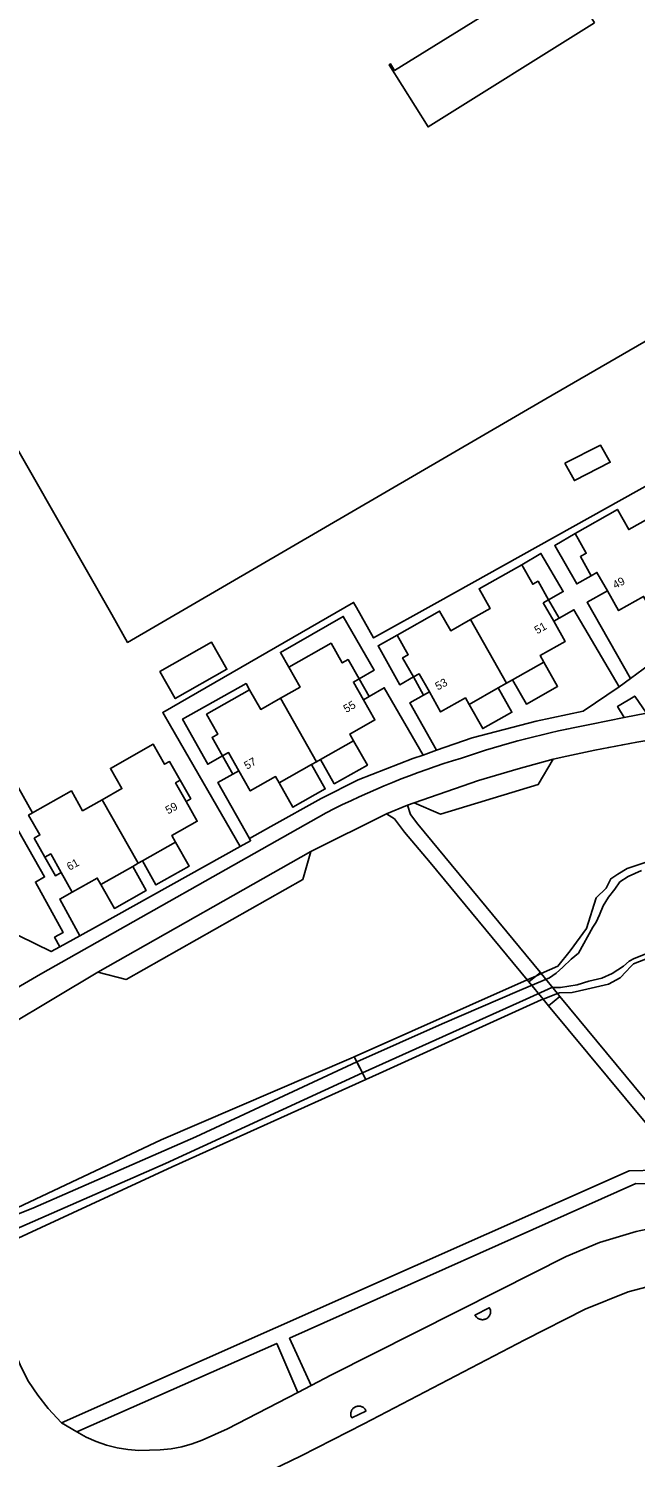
# Model space of a CAD drawing. Extents: x 158132 to 159664, y 385256 to 387218.
# Drawn here: x 158829.4 to 158905.2, y 386531.1 to 386709.7 of the extents above; entities that cross this region are included whole.
import ezdxf

# ---------------------------------------------------------------- set-up
doc = ezdxf.new("R2010")
doc.units = 0
for name, color, linetype in [('IMGEO_Berm_groen', 7, 'Continuous'), ('IMGEO_Dek', 7, 'Continuous'), ('IMGEO_Erf', 7, 'Continuous'), ('IMGEO_Gemengd_bos', 7, 'Continuous'), ('IMGEO_Groenvoorziening', 7, 'Continuous'), ('IMGEO_Oever', 7, 'Continuous'), ('IMGEO_Open_loods', 7, 'Continuous'), ('IMGEO_Pand', 7, 'Continuous'), ('IMGEO_Pand_nummerreeks', 7, 'Continuous'), ('IMGEO_Parkeervlak_open', 7, 'Continuous'), ('IMGEO_Rijbaan_lokaal_gesloten', 7, 'Continuous'), ('IMGEO_Stuw', 7, 'Continuous'), ('IMGEO_Verkeerseiland_gesloten', 7, 'Continuous'), ('IMGEO_Voetpad_open', 7, 'Continuous'), ('IMGEO_Waterloop', 7, 'Continuous')]:
    doc.layers.add(name, color=color, linetype=linetype)

msp = doc.modelspace()

# ---------------------------------------------------------------- linework, layer by layer
at = {"layer": 'IMGEO_Berm_groen'}
for points in [[(158888.13, 386552.01), (158896.53, 386556.23), (158900.72, 386557.98), (158905.3, 386559.36), (158909.03, 386560.17), (158911.81, 386560.55), (158915.94, 386560.75), (158916.6, 386560.75), (158912.81, 386565.3), (158905.26, 386565.37), (158862.01, 386546.04), (158864.7, 386540.13), (158867.23, 386541.45)], [(158863.03, 386539.27), (158860.41, 386545.38), (158835.44, 386534.34), (158836.63, 386533.68), (158837.87, 386533.13), (158839.16, 386532.69), (158840.47, 386532.35), (158841.81, 386532.13), (158843.17, 386532.02), (158844.52, 386532.03), (158845.87, 386532.07), (158847.21, 386532.22), (158848.54, 386532.48), (158849.84, 386532.84), (158851.11, 386533.3), (158854.27, 386534.72)]]:
    msp.add_lwpolyline(points, close=True, dxfattribs=at)
at = {"layer": 'IMGEO_Dek'}
msp.add_lwpolyline([(158893.42, 386591.59), (158893.28, 386591.76), (158892.74, 386591.28), (158891.9, 386590.55), (158893.66, 386588.4), (158894.35, 386587.56), (158895.75, 386588.72), (158895.45, 386589.1)], close=True, dxfattribs=at)
at = {"layer": 'IMGEO_Erf'}
for points in [[(158934.18, 386686.67), (158894, 386663.42), (158841.79, 386632.99), (158839.81, 386636.46), (158826.35, 386660.11)], [(158824.99, 386620.4), (158829.92, 386611.68), (158834.77, 386614.42), (158836.17, 386611.95), (158838.62, 386613.33), (158841.07, 386614.72), (158839.65, 386617.23), (158844.99, 386620.25), (158846.41, 386617.75), (158847.03, 386618.1), (158848.36, 386615.75), (158849.67, 386613.44), (158849.08, 386613.11), (158850.48, 386610.64), (158847.3, 386608.84), (158847.77, 386608.01), (158849.46, 386605.02), (158845.33, 386602.68), (158843.64, 386605.67), (158843.12, 386605.38), (158842.42, 386604.98), (158844.11, 386601.99), (158840.13, 386599.74), (158838.44, 386602.73), (158837.99, 386603.53), (158834.88, 386601.77), (158833.32, 386600.9), (158835.84, 386596.33), (158838.15, 386597.61), (158855.83, 386607.47), (158847.13, 386622.56), (158846.17, 386624.23), (158870.01, 386637.98), (158870.37, 386637.36), (158872.5, 386633.54), (158880.44, 386637.97), (158907.83, 386653.27)], [(158808.08, 386606.17), (158832.23, 386594.34), (158833.32, 386594.94), (158832.66, 386596.14), (158833.74, 386596.73), (158830.27, 386603.03), (158831.43, 386603.67), (158822.65, 386619.06)]]:
    msp.add_lwpolyline(points, dxfattribs=at)
for points in [[(158896.37, 386655.36), (158900.83, 386657.64), (158902.04, 386655.49), (158897.58, 386653.21)], [(158923.8, 386642.26), (158919.5, 386649.38), (158917.3, 386648.14), (158918.62, 386645.8), (158915.52, 386644.04), (158915.99, 386643.21), (158917.67, 386640.24), (158913.41, 386637.83), (158911.73, 386640.8), (158911.3, 386640.55), (158910.53, 386640.12), (158912.21, 386637.15), (158908.33, 386634.96), (158906.66, 386637.93), (158906.2, 386638.73), (158903.08, 386636.96), (158901.69, 386639.42), (158899.16, 386637.99), (158904.56, 386628.48), (158911.71, 386633.74), (158918.74, 386639), (158921.04, 386640.5)], [(158897.65, 386646.61), (158895.11, 386645.11), (158897.86, 386640.29), (158899.68, 386641.32), (158898.32, 386643.71), (158899.06, 386644.12)], [(158893.39, 386644.1), (158890.99, 386642.69), (158892.37, 386640.25), (158893.04, 386640.63), (158894.35, 386638.3), (158896.18, 386639.34)], [(158897.52, 386637.06), (158895.65, 386636), (158894.99, 386635.63), (158896.42, 386633.11), (158893.3, 386631.35), (158893.76, 386630.52), (158895.48, 386627.49), (158891.58, 386625.28), (158889.86, 386628.32), (158889.1, 386627.88), (158888.06, 386627.29), (158889.77, 386624.26), (158889.46, 386624.09), (158886.13, 386622.21), (158884.42, 386625.24), (158883.96, 386626.04), (158880.87, 386624.29), (158879.46, 386626.8), (158878.75, 386626.4), (158877.03, 386625.44), (158880.35, 386619.5), (158884.79, 386621.05), (158892.81, 386623.14), (158898.68, 386624.38), (158903.15, 386627.44)], [(158868.71, 386636.24), (158860.87, 386631.73), (158861.9, 386629.89), (158867.19, 386632.88), (158868.58, 386630.42), (158869.31, 386630.84), (158870.68, 386628.42), (158872.57, 386629.51)], [(158875.43, 386633.9), (158873.05, 386632.56), (158875.76, 386627.7), (158877.48, 386628.66), (158876.12, 386631.05), (158876.82, 386631.45)], [(158845.82, 386629.34), (158852.28, 386633), (158854.19, 386629.63), (158847.73, 386625.97)], [(158851.65, 386624.01), (158857.02, 386627.05), (158856.58, 386627.83), (158848.65, 386623.41), (158851.8, 386617.76), (158853.65, 386618.79), (158852.34, 386621.11), (158853.06, 386621.52)], [(158860.7, 386615.44), (158860.27, 386616.21), (158857.1, 386614.42), (158855.67, 386616.94), (158854.94, 386616.53), (158853.07, 386615.48), (158856.99, 386608.46), (158859.68, 386609.98), (158865.97, 386613.47), (158870.56, 386615.79), (158877.39, 386618.47), (158878.67, 386618.91), (158873.84, 386627.31), (158871.93, 386626.21), (158871.23, 386625.82), (158872.66, 386623.29), (158869.53, 386621.52), (158869.99, 386620.7), (158871.72, 386617.65), (158867.58, 386615.31), (158865.86, 386618.36), (158865.35, 386618.07), (158864.73, 386617.72), (158866.46, 386614.67), (158862.43, 386612.39)]]:
    msp.add_lwpolyline(points, close=True, dxfattribs=at)
at = {"layer": 'IMGEO_Gemengd_bos'}
msp.add_lwpolyline([(158826.35, 386660.11), (158839.81, 386636.46), (158841.79, 386632.99), (158894, 386663.42), (158934.18, 386686.67), (158952.31, 386658.15), (159000, 386688.47), (159011.16, 386695.57), (159011.4, 386697), (159012.14, 386697.47), (159010.3, 386700.29), (159011.17, 386700.87), (158997.52, 386722.16)], dxfattribs=at)
msp.add_lwpolyline([(158900.1, 386710.42), (158879.3, 386697.4), (158874.46, 386705.16), (158874.63, 386705.26), (158875.13, 386704.45), (158895.64, 386717.2), (158895.09, 386718.08), (158895.26, 386718.18)], close=True, dxfattribs=at)
at = {"layer": 'IMGEO_Groenvoorziening'}
for points in [[(158902.97, 386624.98), (158903.79, 386623.6), (158906.57, 386624.16), (158905.11, 386626.27)], [(158894.35, 386587.56), (158895.75, 386588.72), (158895.45, 386589.1), (158893.66, 386588.4)]]:
    msp.add_lwpolyline(points, close=True, dxfattribs=at)
for points in [[(158894.9, 386618.38), (158893.06, 386615.24), (158880.85, 386611.52), (158877.57, 386612.95), (158876.73, 386612.63), (158877.11, 386611.46), (158878.02, 386610.26), (158893.28, 386591.76), (158893.42, 386591.59), (158895.52, 386592.52), (158897.04, 386594.45), (158899.07, 386597.22), (158900.3, 386601.08), (158901.55, 386602.26), (158901.83, 386602.85), (158902.12, 386603.45), (158903, 386604.04), (158904.16, 386604.73), (158907.15, 386605.72)], [(158869.71, 386581.02), (158870.09, 386581.19), (158891.69, 386590.81), (158879.56, 386605.47), (158876.37, 386609.29), (158875.1, 386610.95), (158874.11, 386611.57), (158864.67, 386606.85), (158863.68, 386603.37), (158841.59, 386590.87), (158838.06, 386591.79), (158821.34, 386581.8)], [(158910.42, 386594.96), (158904.95, 386592.82), (158904.56, 386592.44), (158904.05, 386591.87), (158903.27, 386591.08), (158901.81, 386590.29), (158899.14, 386589.66), (158897.31, 386589.25), (158895.7, 386589.2), (158895.45, 386589.1), (158895.75, 386588.72), (158913.24, 386567.6)], [(158818.27, 386573.98), (158823.22, 386558.59), (158827.67, 386544.4), (158828.46, 386542.48), (158829.43, 386540.64), (158830.56, 386538.9), (158831.85, 386537.27), (158833.53, 386535.48), (158904.42, 386566.95), (158911.33, 386567.1), (158894.35, 386587.56), (158893.66, 386588.4), (158893.44, 386588.31), (158873.2, 386579.11), (158871.54, 386578.36), (158847.34, 386567.44), (158827.03, 386558.04), (158825.5, 386558.41), (158824.82, 386559.92), (158825.76, 386561.3), (158845.97, 386570.81), (158869.71, 386581.02)], [(158936.96, 386525.53), (158923.1, 386553.6), (158923.02, 386553.59), (158913.93, 386553.63), (158910.67, 386553.29), (158907.44, 386552.68), (158904.28, 386551.82), (158898.92, 386549.67), (158891.4, 386545.83), (158871.3, 386535.33), (158863.44, 386531.35), (158857.17, 386528.29)]]:
    msp.add_lwpolyline(points, dxfattribs=at)
msp.add_arc((158937.68, 386434.2), 189.08, 85.8307, 103.0757, dxfattribs=at)
at = {"layer": 'IMGEO_Oever'}
for points in [[(158907.15, 386605.72), (158904.16, 386604.73), (158903, 386604.04), (158902.12, 386603.45), (158901.83, 386602.85), (158901.55, 386602.26), (158900.3, 386601.08), (158899.07, 386597.22), (158897.04, 386594.45), (158895.52, 386592.52), (158893.42, 386591.59), (158892.74, 386591.28), (158891.69, 386590.81), (158870.09, 386581.19), (158870.4, 386580.59), (158881.06, 386585.32), (158890.71, 386589.5), (158894.45, 386591.05), (158895.3, 386591.67), (158896.12, 386592.39), (158897.16, 386593.38), (158898.09, 386594.17), (158899.89, 386597.41), (158900.27, 386598.01), (158900.7, 386598.93), (158901.16, 386600.05), (158901.83, 386601.16), (158902.61, 386602.16), (158903.25, 386603.07), (158904.27, 386603.75), (158905.97, 386604.5)], [(158906.39, 386594.02), (158905.05, 386593.49), (158904.42, 386593.17), (158903.71, 386592.54), (158902.3, 386591.62), (158900.98, 386591.04), (158899.37, 386590.65), (158897.93, 386590.21), (158895.82, 386589.86), (158894.76, 386589.84), (158891.54, 386588.41), (158871.12, 386579.19), (158871.54, 386578.36), (158873.2, 386579.11), (158893.44, 386588.31), (158893.66, 386588.4), (158895.45, 386589.1), (158895.7, 386589.2), (158897.31, 386589.25), (158899.14, 386589.66), (158901.81, 386590.29), (158903.27, 386591.08), (158904.05, 386591.87), (158904.56, 386592.44), (158904.95, 386592.82), (158910.42, 386594.96)]]:
    msp.add_lwpolyline(points, dxfattribs=at)
msp.add_lwpolyline([(158871.54, 386578.36), (158871.12, 386579.19), (158846.53, 386567.85), (158826.88, 386559.26), (158826.46, 386559.47), (158826.22, 386560.01), (158826.18, 386560.43), (158826.51, 386560.91), (158829.95, 386562.3), (158850.3, 386571.19), (158870.4, 386580.59), (158870.09, 386581.19), (158869.71, 386581.02), (158845.97, 386570.81), (158825.76, 386561.3), (158824.82, 386559.92), (158825.5, 386558.41), (158827.03, 386558.04), (158847.34, 386567.44)], close=True, dxfattribs=at)
at = {"layer": 'IMGEO_Open_loods'}
msp.add_lwpolyline([(158900.1, 386710.42), (158895.26, 386718.18), (158895.09, 386718.08), (158895.64, 386717.2), (158875.13, 386704.45), (158874.63, 386705.26), (158874.46, 386705.16), (158879.3, 386697.4)], close=True, dxfattribs=at)
at = {"layer": 'IMGEO_Pand'}
for points in [[(158896.37, 386655.36), (158897.58, 386653.21), (158902.04, 386655.49), (158900.83, 386657.64)], [(158906.82, 386648.48), (158904.36, 386647.09), (158902.94, 386649.6), (158897.65, 386646.61), (158899.06, 386644.12), (158898.32, 386643.71), (158899.68, 386641.32), (158900.39, 386641.72), (158901.69, 386639.42), (158903.08, 386636.96), (158906.2, 386638.73), (158906.66, 386637.93), (158910.53, 386640.12), (158911.3, 386640.55)], [(158893.69, 386637.93), (158894.35, 386638.3), (158893.04, 386640.63), (158892.37, 386640.25), (158890.99, 386642.69), (158885.68, 386639.69), (158887.07, 386637.23), (158884.6, 386635.83), (158889.1, 386627.88), (158889.86, 386628.32), (158893.76, 386630.52), (158893.3, 386631.35), (158896.42, 386633.11), (158894.99, 386635.63)], [(158884.6, 386635.83), (158882.13, 386634.44), (158880.74, 386636.9), (158875.43, 386633.9), (158876.82, 386631.45), (158876.12, 386631.05), (158877.48, 386628.66), (158878.18, 386629.06), (158879.46, 386626.8), (158880.87, 386624.29), (158883.96, 386626.04), (158884.42, 386625.24), (158888.06, 386627.29), (158889.1, 386627.88)], [(158847.73, 386625.97), (158854.19, 386629.63), (158852.28, 386633), (158845.82, 386629.34)], [(158871.23, 386625.82), (158869.98, 386628.03), (158870.68, 386628.42), (158869.31, 386630.84), (158868.58, 386630.42), (158867.19, 386632.88), (158861.9, 386629.89), (158863.32, 386627.39), (158860.86, 386626), (158865.35, 386618.07), (158865.86, 386618.36), (158869.99, 386620.7), (158869.53, 386621.52), (158872.66, 386623.29)], [(158860.86, 386626), (158858.4, 386624.61), (158857.02, 386627.05), (158851.65, 386624.01), (158853.06, 386621.52), (158852.34, 386621.11), (158853.65, 386618.79), (158854.39, 386619.21), (158855.67, 386616.94), (158857.1, 386614.42), (158860.27, 386616.21), (158860.7, 386615.44), (158864.73, 386617.72), (158865.35, 386618.07)], [(158847.77, 386615.42), (158848.36, 386615.75), (158847.03, 386618.1), (158846.41, 386617.75), (158844.99, 386620.25), (158839.65, 386617.23), (158841.07, 386614.72), (158838.62, 386613.33), (158843.12, 386605.38), (158843.64, 386605.67), (158847.77, 386608.01), (158847.3, 386608.84), (158850.48, 386610.64), (158849.08, 386613.11)], [(158838.62, 386613.33), (158836.17, 386611.95), (158834.77, 386614.42), (158829.92, 386611.68), (158829.43, 386611.4), (158830.84, 386608.92), (158830.13, 386608.52), (158831.47, 386606.15), (158832.18, 386606.55), (158833.49, 386604.23), (158834.88, 386601.77), (158837.99, 386603.53), (158838.44, 386602.73), (158842.42, 386604.98), (158843.12, 386605.38)]]:
    msp.add_lwpolyline(points, close=True, dxfattribs=at)
at = {"layer": 'IMGEO_Parkeervlak_open'}
for points in [[(158894.9, 386618.38), (158890.53, 386617.17), (158885.6, 386615.73), (158877.57, 386612.95), (158880.85, 386611.52), (158893.06, 386615.24)], [(158864.67, 386606.85), (158838.06, 386591.79), (158841.59, 386590.87), (158863.68, 386603.37)]]:
    msp.add_lwpolyline(points, close=True, dxfattribs=at)
at = {"layer": 'IMGEO_Rijbaan_lokaal_gesloten'}
for points in [[(158953.96, 386625.78), (158944.85, 386626.47), (158936.8, 386626.71), (158925.72, 386626.16), (158917.97, 386625.61), (158906.57, 386624.16), (158903.79, 386623.6), (158899.7, 386622.78)], [(158821.34, 386581.8), (158838.06, 386591.79), (158864.67, 386606.85), (158874.11, 386611.57), (158876.73, 386612.63), (158877.57, 386612.95), (158885.6, 386615.73), (158890.53, 386617.17), (158894.9, 386618.38)], [(158866.59, 386611.69), (158830.89, 386591.54), (158824.65, 386587.92), (158820.79, 386585.6), (158819.2, 386584.7), (158818.52, 386584.29)], [(158857.17, 386528.29), (158863.44, 386531.35), (158871.3, 386535.33), (158891.4, 386545.83), (158898.92, 386549.67), (158904.28, 386551.82), (158907.44, 386552.68), (158910.67, 386553.29), (158913.93, 386553.63), (158923.02, 386553.59), (158923.1, 386553.6), (158925.12, 386553.7), (158925.18, 386553.7), (158927.78, 386553.93), (158944.36, 386560.03)], [(158905.3, 386559.36), (158900.72, 386557.98), (158896.53, 386556.23), (158888.13, 386552.01), (158867.23, 386541.45), (158864.7, 386540.13), (158863.03, 386539.27), (158854.27, 386534.72), (158851.11, 386533.3), (158849.84, 386532.84), (158848.54, 386532.48), (158847.21, 386532.22), (158845.87, 386532.07), (158844.52, 386532.03), (158843.17, 386532.02), (158841.81, 386532.13), (158840.47, 386532.35), (158839.16, 386532.69), (158837.87, 386533.13), (158836.63, 386533.68), (158835.44, 386534.34), (158833.53, 386535.48), (158831.85, 386537.27), (158830.56, 386538.9), (158829.43, 386540.64), (158828.46, 386542.48)]]:
    msp.add_lwpolyline(points, dxfattribs=at)
for points in [[(158887.03, 386548.97), (158887, 386548.89), (158886.95, 386548.82), (158886.9, 386548.75), (158886.84, 386548.68), (158886.78, 386548.62), (158886.71, 386548.56), (158886.64, 386548.51), (158886.56, 386548.47), (158886.48, 386548.43), (158886.4, 386548.4), (158886.31, 386548.38), (158886.23, 386548.36), (158886.14, 386548.35), (158886.05, 386548.35), (158885.96, 386548.36), (158885.88, 386548.38), (158885.79, 386548.4), (158885.71, 386548.43), (158885.63, 386548.47), (158885.55, 386548.51), (158885.48, 386548.56), (158885.41, 386548.62), (158885.35, 386548.68), (158885.16, 386548.9), (158886.94, 386549.84), (158887.09, 386549.58), (158887.11, 386549.49), (158887.11, 386549.41), (158887.11, 386549.32), (158887.1, 386549.23), (158887.09, 386549.14), (158887.06, 386549.06)], [(158871.43, 386537.18), (158871.54, 386536.9), (158869.8, 386536.09), (158869.66, 386536.33), (158869.65, 386536.42), (158869.64, 386536.5), (158869.64, 386536.59), (158869.65, 386536.68), (158869.67, 386536.76), (158869.69, 386536.85), (158869.72, 386536.93), (158869.75, 386537.01), (158869.8, 386537.08), (158869.85, 386537.15), (158869.9, 386537.22), (158869.96, 386537.28), (158870.03, 386537.34), (158870.1, 386537.39), (158870.17, 386537.43), (158870.25, 386537.47), (158870.33, 386537.5), (158870.42, 386537.52), (158870.5, 386537.54), (158870.59, 386537.55), (158870.67, 386537.55), (158870.76, 386537.54), (158870.85, 386537.53), (158870.93, 386537.51), (158871.01, 386537.48), (158871.09, 386537.45), (158871.17, 386537.41), (158871.24, 386537.36), (158871.31, 386537.31), (158871.37, 386537.25)]]:
    msp.add_lwpolyline(points, close=True, dxfattribs=at)
for centre, radius, start, end in [((158921.4, 386506.5), 118.28, 100.5703, 108.7091), ((158937.68, 386434.2), 189.08, 85.8307, 103.0757), ((158912.82, 386521.96), 100.94, 106.9126, 117.2584)]:
    msp.add_arc(centre, radius, start, end, dxfattribs=at)
at = {"layer": 'IMGEO_Stuw'}
msp.add_lwpolyline([(158871.54, 386578.36), (158870.09, 386581.19)], dxfattribs=at)
at = {"layer": 'IMGEO_Verkeerseiland_gesloten'}
for points in [[(158885.35, 386548.68), (158885.41, 386548.62), (158885.48, 386548.56), (158885.55, 386548.51), (158885.63, 386548.47), (158885.71, 386548.43), (158885.79, 386548.4), (158885.88, 386548.38), (158885.96, 386548.36), (158886.05, 386548.35), (158886.14, 386548.35), (158886.23, 386548.36), (158886.31, 386548.38), (158886.4, 386548.4), (158886.48, 386548.43), (158886.56, 386548.47), (158886.64, 386548.51), (158886.71, 386548.56), (158886.78, 386548.62), (158886.84, 386548.68), (158886.9, 386548.75), (158886.95, 386548.82), (158887, 386548.89), (158887.03, 386548.97), (158887.06, 386549.06), (158887.09, 386549.14), (158887.1, 386549.23), (158887.11, 386549.32), (158887.11, 386549.41), (158887.11, 386549.49), (158887.09, 386549.58), (158886.94, 386549.84), (158885.16, 386548.9)], [(158871.43, 386537.18), (158871.37, 386537.25), (158871.31, 386537.31), (158871.24, 386537.36), (158871.17, 386537.41), (158871.09, 386537.45), (158871.01, 386537.48), (158870.93, 386537.51), (158870.85, 386537.53), (158870.76, 386537.54), (158870.67, 386537.55), (158870.59, 386537.55), (158870.5, 386537.54), (158870.42, 386537.52), (158870.33, 386537.5), (158870.25, 386537.47), (158870.17, 386537.43), (158870.1, 386537.39), (158870.03, 386537.34), (158869.96, 386537.28), (158869.9, 386537.22), (158869.85, 386537.15), (158869.8, 386537.08), (158869.75, 386537.01), (158869.72, 386536.93), (158869.69, 386536.85), (158869.67, 386536.76), (158869.65, 386536.68), (158869.64, 386536.59), (158869.64, 386536.5), (158869.65, 386536.42), (158869.66, 386536.33), (158869.8, 386536.09), (158871.54, 386536.9)]]:
    msp.add_lwpolyline(points, close=True, dxfattribs=at)
at = {"layer": 'IMGEO_Voetpad_open'}
for points in [[(158907.83, 386653.27), (158880.44, 386637.97), (158872.5, 386633.54), (158870.37, 386637.36), (158870.01, 386637.98), (158846.17, 386624.23), (158847.13, 386622.56), (158855.83, 386607.47), (158857.14, 386608.19), (158856.99, 386608.46), (158853.07, 386615.48), (158854.94, 386616.53), (158853.65, 386618.79), (158851.8, 386617.76), (158848.65, 386623.41), (158856.58, 386627.83), (158857.02, 386627.05), (158858.4, 386624.61), (158860.86, 386626), (158863.32, 386627.39), (158861.9, 386629.89), (158860.87, 386631.73), (158868.71, 386636.24), (158872.57, 386629.51), (158870.68, 386628.42), (158871.93, 386626.21), (158873.84, 386627.31), (158878.67, 386618.91), (158880.35, 386619.5), (158877.03, 386625.44), (158878.75, 386626.4), (158877.48, 386628.66), (158875.76, 386627.7), (158873.05, 386632.56), (158875.43, 386633.9), (158880.74, 386636.9), (158882.13, 386634.44), (158884.6, 386635.83), (158887.07, 386637.23), (158885.68, 386639.69), (158890.99, 386642.69), (158893.39, 386644.1), (158896.18, 386639.34), (158894.35, 386638.3), (158895.65, 386636), (158897.52, 386637.06), (158903.15, 386627.44), (158904.56, 386628.48), (158899.16, 386637.99), (158901.69, 386639.42), (158900.39, 386641.72), (158899.68, 386641.32), (158897.86, 386640.29), (158895.11, 386645.11), (158897.65, 386646.61), (158902.94, 386649.6), (158904.36, 386647.09), (158906.82, 386648.48)], [(158911.71, 386633.74), (158904.56, 386628.48), (158903.15, 386627.44), (158898.68, 386624.38), (158892.81, 386623.14), (158884.79, 386621.05), (158880.35, 386619.5), (158878.67, 386618.91), (158877.39, 386618.47), (158870.56, 386615.79), (158865.97, 386613.47), (158859.68, 386609.98), (158856.99, 386608.46), (158857.14, 386608.19), (158855.83, 386607.47), (158838.15, 386597.61), (158835.84, 386596.33), (158833.32, 386594.94), (158832.23, 386594.34), (158808.08, 386606.17)], [(158899.7, 386622.78), (158903.79, 386623.6), (158902.97, 386624.98), (158905.11, 386626.27), (158906.57, 386624.16)], [(158818.52, 386584.29), (158819.2, 386584.7), (158820.79, 386585.6), (158824.65, 386587.92), (158830.89, 386591.54), (158866.59, 386611.69)], [(158913.24, 386567.6), (158895.75, 386588.72), (158894.35, 386587.56), (158911.33, 386567.1), (158904.42, 386566.95), (158833.53, 386535.48), (158835.44, 386534.34), (158860.41, 386545.38), (158863.03, 386539.27), (158864.7, 386540.13), (158862.01, 386546.04), (158905.26, 386565.37)]]:
    msp.add_lwpolyline(points, dxfattribs=at)
for points in [[(158893.69, 386637.93), (158894.99, 386635.63), (158895.65, 386636), (158894.35, 386638.3)], [(158893.76, 386630.52), (158889.86, 386628.32), (158891.58, 386625.28), (158895.48, 386627.49)], [(158871.23, 386625.82), (158871.93, 386626.21), (158870.68, 386628.42), (158869.98, 386628.03)], [(158878.18, 386629.06), (158877.48, 386628.66), (158878.75, 386626.4), (158879.46, 386626.8)], [(158888.06, 386627.29), (158884.42, 386625.24), (158886.13, 386622.21), (158889.46, 386624.09), (158889.77, 386624.26)], [(158824.99, 386620.4), (158822.65, 386619.06), (158831.43, 386603.67), (158830.27, 386603.03), (158833.74, 386596.73), (158832.66, 386596.14), (158833.32, 386594.94), (158835.84, 386596.33), (158833.32, 386600.9), (158834.88, 386601.77), (158833.49, 386604.23), (158832.78, 386603.83), (158831.47, 386606.15), (158830.13, 386608.52), (158830.84, 386608.92), (158829.43, 386611.4), (158829.92, 386611.68)], [(158853.65, 386618.79), (158854.94, 386616.53), (158855.67, 386616.94), (158854.39, 386619.21)], [(158869.99, 386620.7), (158865.86, 386618.36), (158867.58, 386615.31), (158871.72, 386617.65)], [(158864.73, 386617.72), (158860.7, 386615.44), (158862.43, 386612.39), (158866.46, 386614.67)], [(158849.08, 386613.11), (158849.67, 386613.44), (158848.36, 386615.75), (158847.77, 386615.42)], [(158878.02, 386610.26), (158877.11, 386611.46), (158876.73, 386612.63), (158874.11, 386611.57), (158875.1, 386610.95), (158876.37, 386609.29), (158879.56, 386605.47), (158891.69, 386590.81), (158892.74, 386591.28), (158893.42, 386591.59), (158893.28, 386591.76)], [(158831.47, 386606.15), (158832.78, 386603.83), (158833.49, 386604.23), (158832.18, 386606.55)], [(158847.77, 386608.01), (158843.64, 386605.67), (158845.33, 386602.68), (158849.46, 386605.02)], [(158842.42, 386604.98), (158838.44, 386602.73), (158840.13, 386599.74), (158844.11, 386601.99)], [(158893.42, 386591.59), (158892.74, 386591.28), (158891.69, 386590.81), (158891.9, 386590.55), (158893.66, 386588.4), (158895.45, 386589.1)], [(158894.35, 386587.56), (158895.75, 386588.72), (158895.45, 386589.1), (158893.66, 386588.4)]]:
    msp.add_lwpolyline(points, close=True, dxfattribs=at)
for centre, radius, start, end in [((158921.4, 386506.5), 118.28, 100.5703, 108.7091), ((158912.82, 386521.96), 100.94, 106.9126, 117.2584)]:
    msp.add_arc(centre, radius, start, end, dxfattribs=at)
at = {"layer": 'IMGEO_Waterloop'}
msp.add_lwpolyline([(158905.97, 386604.5), (158904.27, 386603.75), (158903.25, 386603.07), (158902.61, 386602.16), (158901.83, 386601.16), (158901.16, 386600.05), (158900.7, 386598.93), (158900.27, 386598.01), (158899.89, 386597.41), (158898.09, 386594.17), (158897.16, 386593.38), (158896.12, 386592.39), (158895.3, 386591.67), (158894.45, 386591.05), (158890.71, 386589.5), (158881.06, 386585.32), (158870.4, 386580.59), (158871.12, 386579.19), (158891.54, 386588.41), (158894.76, 386589.84), (158895.82, 386589.86), (158897.93, 386590.21), (158899.37, 386590.65), (158900.98, 386591.04), (158902.3, 386591.62), (158903.71, 386592.54), (158904.42, 386593.17), (158905.05, 386593.49), (158906.39, 386594.02)], dxfattribs=at)
msp.add_lwpolyline([(158871.12, 386579.19), (158870.4, 386580.59), (158850.3, 386571.19), (158829.95, 386562.3), (158826.51, 386560.91), (158826.18, 386560.43), (158826.22, 386560.01), (158826.46, 386559.47), (158826.88, 386559.26), (158846.53, 386567.85)], close=True, dxfattribs=at)

# ---------------------------------------------------------------- texts
at = {"layer": 'IMGEO_Pand_nummerreeks'}
for s, rotation, p in [('49', 28.625, (158902.69, 386639.63)), ('51', 29.5131, (158892.92, 386633.98)), ('53', 28.2697, (158880.52, 386626.97)), ('55', 30.0803, (158869.09, 386624.15)), ('57', 29.6792, (158856.68, 386617.06)), ('59', 28.7338, (158846.84, 386611.48)), ('61', 28.7396, (158834.53, 386604.44))]:
    msp.add_text(s, height=1, rotation=rotation, dxfattribs=at).set_placement(p)

doc.saveas('drawing.dxf')
